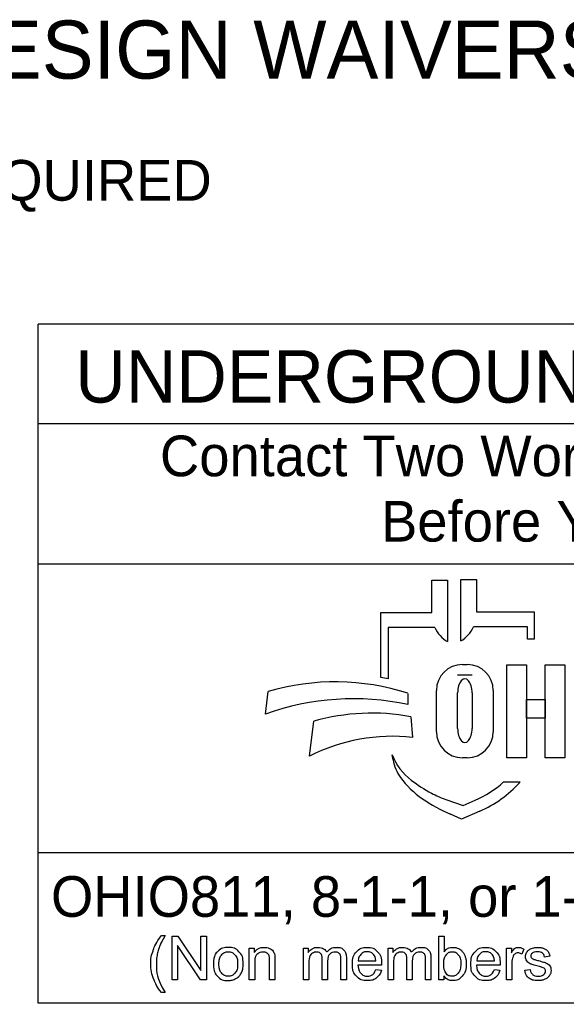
# Model space of a CAD drawing. Extents: x 0 to 34, y 0 to 22.
# Drawn here: x 2.914 to 4.796, y 2.143 to 5.529 of the extents above; entities that cross this region are included whole.
import ezdxf

# ---------------------------------------------------------------- set-up
doc = ezdxf.new("R2010")
doc.units = 0
doc.layers.add('SH_Data', color=7, linetype='Continuous')
doc.layers.add('SH_Text', color=7, linetype='Continuous')

msp = doc.modelspace()

# ---------------------------------------------------------------- linework, layer by layer
at = {"layer": 'SH_Data'}
for p, q in [((2.9775, 2.1428), (2.9775, 4.4803)), ((7.2275, 4.4803), (2.9775, 4.4803)), ((2.9775, 4.1387), (7.2275, 4.1387)), ((2.9775, 3.6553), (7.2275, 3.6553)), ((7.2275, 2.6607), (2.9775, 2.6607)), ((7.2275, 2.1428), (2.9775, 2.1428))]:
    msp.add_line(p, q, dxfattribs=at)
at = {"layer": 'SH_Text'}
for p, q in [((4.3335, 3.4883), (4.3335, 3.5998)), ((4.3335, 3.5998), (4.3872, 3.5998)), ((4.3872, 3.5998), (4.3872, 3.3877)), ((4.4329, 3.39), (4.4329, 3.6021)), ((4.4329, 3.6021), (4.4865, 3.6021)), ((4.4865, 3.6021), (4.4865, 3.4906)), ((4.1576, 3.2644), (4.1576, 3.4883)), ((4.1576, 3.4883), (4.3335, 3.4883)), ((4.4865, 3.4906), (4.6857, 3.4906)), ((4.6857, 3.4906), (4.6857, 3.3968)), ((4.1828, 3.4369), (4.1828, 3.26)), ((4.3439, 3.4369), (4.1828, 3.4369)), ((4.6625, 3.4392), (4.4761, 3.4392)), ((4.6625, 3.3968), (4.6625, 3.4392)), ((4.6857, 3.3968), (4.6625, 3.3968)), ((4.4385, 3.3091), (4.4551, 3.3091)), ((4.4718, 3.2721), (4.422, 3.2721)), ((4.3491, 3.0776), (4.3491, 3.2196)), ((4.5445, 3.2196), (4.5445, 3.0776)), ((3.7602, 3.1381), (3.7696, 3.2162)), ((4.2509, 3.2097), (4.2509, 3.1709)), ((4.422, 3.089), (4.422, 3.2114)), ((4.4718, 3.2114), (4.4718, 3.089)), ((4.2608, 3.1291), (4.2671, 3.0582)), ((3.912, 2.9936), (3.9267, 3.1137)), ((4.1997, 2.9807), (4.1967, 2.9986)), ((4.4551, 2.9882), (4.4385, 2.9882)), ((4.58, 2.9048), (4.6375, 2.9048)), ((4.3816, 2.8444), (4.441, 2.8239)), ((4.441, 2.8239), (4.4821, 2.8417)), ((4.435, 2.7769), (4.3976, 2.7934)), ((4.4983, 2.8044), (4.435, 2.7769))]:
    msp.add_line(p, q, dxfattribs=at)
for points in [[(4.591, 3.3081), (4.6589, 3.3081), (4.6589, 2.9881), (4.591, 2.9881)], [(4.7231, 3.3081), (4.7911, 3.3081), (4.7911, 2.9881), (4.7231, 2.9881)], [(4.6589, 3.1882), (4.7231, 3.1882), (4.7231, 3.1242), (4.6589, 3.1242)]]:
    msp.add_lwpolyline(points, close=True, dxfattribs=at)
for points in [[(3.4021, 2.3766), (3.4153, 2.3766)], [(3.4389, 2.2239), (3.4389, 2.3741), (3.4592, 2.3741), (3.5382, 2.2561), (3.5382, 2.3741), (3.5572, 2.3741), (3.5572, 2.2239), (3.5369, 2.2239), (3.4579, 2.3419), (3.4579, 2.2239), (3.4389, 2.2239)], [(4.3743, 2.2239), (4.3573, 2.2239), (4.3573, 2.3741), (4.3757, 2.3741), (4.3757, 2.3206)], [(3.7048, 2.2239), (3.7048, 2.3328), (3.7214, 2.3328), (3.7214, 2.3173)], [(3.8912, 2.2239), (3.8912, 2.3328), (3.9077, 2.3328), (3.9077, 2.3174)], [(4.1826, 2.2239), (4.1826, 2.3328), (4.1991, 2.3328), (4.1991, 2.3174)], [(4.5904, 2.2239), (4.5904, 2.3328), (4.607, 2.3328), (4.607, 2.3163)], [(4.6495, 2.3293), (4.643, 2.3122)], [(4.7394, 2.3046), (4.7213, 2.3022)], [(3.7233, 2.2833), (3.7233, 2.2239), (3.7048, 2.2239)], [(3.7932, 2.2908), (3.7932, 2.2239), (3.7748, 2.2239), (3.7748, 2.2901)], [(3.9097, 2.2803), (3.9097, 2.2239), (3.8912, 2.2239)], [(3.9743, 2.2871), (3.9743, 2.2239), (3.9559, 2.2239), (3.9559, 2.2946)], [(4.0388, 2.2986), (4.0388, 2.2239), (4.0203, 2.2239), (4.0203, 2.2924)], [(4.16, 2.2736), (4.0788, 2.2736)], [(4.0799, 2.2887), (4.1406, 2.2887)], [(4.201, 2.2803), (4.201, 2.2239), (4.1826, 2.2239)], [(4.2657, 2.2871), (4.2657, 2.2239), (4.2473, 2.2239), (4.2473, 2.2946)], [(4.3301, 2.2986), (4.3301, 2.2239), (4.3117, 2.2239), (4.3117, 2.2924)], [(4.568, 2.2736), (4.4868, 2.2736)], [(4.4879, 2.2887), (4.5486, 2.2887)], [(4.6088, 2.2809), (4.6088, 2.2239), (4.5904, 2.2239)], [(4.1404, 2.2591), (4.1595, 2.2567)], [(4.3743, 2.2375), (4.3743, 2.2239)], [(4.5484, 2.2591), (4.5675, 2.2567)], [(4.653, 2.2564), (4.6712, 2.2593)], [(3.4153, 2.1798), (3.4021, 2.1798)]]:
    msp.add_lwpolyline(points, dxfattribs=at)
for centre, radius, start, end in [((4.4353, 3.4736), 0.0985, 201.9296, 240.7469), ((4.3847, 3.476), 0.0985, 299.2531, 338.0704), ((4.4385, 3.2196), 0.0895, 90, 180), ((4.4551, 3.2196), 0.0895, 0, 90), ((4.0295, 2.4554), 0.8191, 79.2074, 81.0007), ((3.9997, 2.4302), 0.8191, 72.1402, 106.3144), ((4.0628, 2.2991), 0.8919, 77.8238, 109.8274), ((4.1267, 2.4094), 0.7322, 79.44, 105.8467), ((4.1987, 2.4262), 0.6357, 83.8248, 116.8021), ((4.4385, 3.0776), 0.0895, 180, 270), ((4.4551, 3.0776), 0.0895, 270, 0), ((4.3841, 3.0707), 0.2008, 201.0457, 232.5314), ((4.341, 3.0048), 0.1433, 189.6817, 216.0884), ((4.4747, 3.1022), 0.3088, 216.0884, 235.7167), ((4.5766, 3.3219), 0.5173, 232.5314, 241.794), ((4.3387, 3.1722), 0.3602, 293.4582, 312.0712), ((4.3387, 3.1722), 0.401, 293.4582, 317.8286), ((4.6412, 3.3465), 0.6044, 235.7167, 246.2325), ((4.4914, 3.1631), 0.3371, 241.794, 250.9821)]:
    msp.add_arc(centre, radius, start, end, dxfattribs=at)
for centre, start_param, end_param in [((4.4469, 3.2114), 4.712389, 7.853982), ((4.4469, 3.089), 1.570796, 4.712389)]:
    msp.add_ellipse(centre, major_axis=(0, 0.0484), ratio=0.514403, start_param=start_param, end_param=end_param, dxfattribs=at)
for points in [[(3.4021, 2.1798), (3.3869, 2.199), (3.3763, 2.2248), (3.3657, 2.2506), (3.3657, 2.2783), (3.3657, 2.3026), (3.3736, 2.325), (3.3829, 2.3509), (3.4021, 2.3766)], [(3.4153, 2.3766), (3.4029, 2.3553), (3.3989, 2.3462), (3.3927, 2.332), (3.3891, 2.3167), (3.3847, 2.2975), (3.3847, 2.2782), (3.3847, 2.2289), (3.4153, 2.1798)], [(3.5814, 2.2783), (3.5814, 2.3085), (3.5981, 2.3231), (3.6122, 2.3352), (3.6323, 2.3352), (3.6547, 2.3352), (3.669, 2.3205), (3.6832, 2.3058), (3.6832, 2.2799), (3.6832, 2.2589), (3.6769, 2.2469), (3.6706, 2.2348), (3.6586, 2.2282), (3.6466, 2.2215), (3.6323, 2.2215), (3.6095, 2.2215), (3.5954, 2.2362), (3.5814, 2.2508), (3.5814, 2.2783)], [(3.6003, 2.2783), (3.6003, 2.2574), (3.6094, 2.247), (3.6185, 2.2366), (3.6323, 2.2366), (3.646, 2.2366), (3.6551, 2.2471), (3.6642, 2.2575), (3.6642, 2.279), (3.6642, 2.2991), (3.6551, 2.3095), (3.6459, 2.3199), (3.6323, 2.3199), (3.6185, 2.3199), (3.6094, 2.3096), (3.6003, 2.2992), (3.6003, 2.2783)], [(3.7214, 2.3173), (3.7334, 2.3352), (3.756, 2.3352), (3.7659, 2.3352), (3.7741, 2.3316), (3.7823, 2.3281), (3.7864, 2.3224), (3.7905, 2.3166), (3.7922, 2.3087), (3.7932, 2.3036), (3.7932, 2.2908)], [(3.7748, 2.2901), (3.7748, 2.3013), (3.7726, 2.3069), (3.7705, 2.3125), (3.765, 2.3158), (3.7595, 2.3191), (3.7521, 2.3191), (3.7404, 2.3191), (3.7318, 2.3117), (3.7233, 2.3042), (3.7233, 2.2833)], [(3.9077, 2.3174), (3.9128, 2.3254), (3.9214, 2.3303), (3.9299, 2.3352), (3.9407, 2.3352), (3.9528, 2.3352), (3.9606, 2.3301), (3.9683, 2.3251), (3.9715, 2.3161), (3.9844, 2.3352), (4.0051, 2.3352), (4.0213, 2.3352), (4.03, 2.3262), (4.0388, 2.3172), (4.0388, 2.2986)], [(3.9559, 2.2946), (3.9559, 2.3069), (3.9514, 2.313), (3.9469, 2.3191), (3.9366, 2.3191), (3.9288, 2.3191), (3.9222, 2.315), (3.9156, 2.311), (3.9126, 2.3031), (3.9097, 2.2952), (3.9097, 2.2803)], [(4.0203, 2.2924), (4.0203, 2.3035), (4.0185, 2.3083), (4.0168, 2.3132), (4.012, 2.3162), (4.0073, 2.3191), (4.001, 2.3191), (3.9895, 2.3191), (3.9819, 2.3115), (3.9743, 2.3039), (3.9743, 2.2871)], [(4.1595, 2.2567), (4.155, 2.24), (4.1428, 2.2307), (4.1306, 2.2215), (4.1117, 2.2215), (4.0878, 2.2215), (4.0738, 2.2362), (4.0598, 2.2509), (4.0598, 2.2774), (4.0598, 2.3049), (4.074, 2.32), (4.0881, 2.3352), (4.1106, 2.3352), (4.1324, 2.3352), (4.1463, 2.3203), (4.1601, 2.3055), (4.1601, 2.2785), (4.1601, 2.2769), (4.16, 2.2736)], [(4.1406, 2.2887), (4.1394, 2.3025), (4.1337, 2.3094), (4.1249, 2.3201), (4.1108, 2.3201), (4.0981, 2.3201), (4.0894, 2.3115), (4.0808, 2.303), (4.0799, 2.2887)], [(4.1991, 2.3174), (4.2042, 2.3254), (4.2127, 2.3303), (4.2212, 2.3352), (4.2321, 2.3352), (4.2442, 2.3352), (4.2519, 2.3301), (4.2597, 2.3251), (4.2628, 2.3161), (4.2758, 2.3352), (4.2965, 2.3352), (4.3127, 2.3352), (4.3214, 2.3262), (4.3301, 2.3172), (4.3301, 2.2986)], [(4.2473, 2.2946), (4.2473, 2.3069), (4.2428, 2.313), (4.2383, 2.3191), (4.228, 2.3191), (4.2202, 2.3191), (4.2136, 2.315), (4.207, 2.311), (4.204, 2.3031), (4.201, 2.2952), (4.201, 2.2803)], [(4.3117, 2.2924), (4.3117, 2.3035), (4.3099, 2.3083), (4.3081, 2.3132), (4.3034, 2.3162), (4.2987, 2.3191), (4.2923, 2.3191), (4.2809, 2.3191), (4.2733, 2.3115), (4.2657, 2.3039), (4.2657, 2.2871)], [(4.3741, 2.2792), (4.3741, 2.2596), (4.3794, 2.2509), (4.3881, 2.2366), (4.4029, 2.2366), (4.415, 2.2366), (4.4238, 2.2471), (4.4326, 2.2576), (4.4326, 2.2784), (4.4326, 2.2998), (4.4241, 2.3099), (4.4157, 2.3201), (4.4038, 2.3201), (4.3917, 2.3201), (4.3829, 2.3096), (4.3741, 2.299), (4.3741, 2.2792)], [(4.3757, 2.3206), (4.3874, 2.3352), (4.4055, 2.3352), (4.4155, 2.3352), (4.4245, 2.3311), (4.4335, 2.3271), (4.4392, 2.3198), (4.445, 2.3124), (4.4483, 2.3021), (4.4516, 2.2918), (4.4516, 2.28), (4.4516, 2.252), (4.4378, 2.2368), (4.4239, 2.2215), (4.4046, 2.2215), (4.3853, 2.2215), (4.3743, 2.2375)], [(4.5675, 2.2567), (4.563, 2.24), (4.5508, 2.2307), (4.5386, 2.2215), (4.5196, 2.2215), (4.4958, 2.2215), (4.4818, 2.2362), (4.4678, 2.2509), (4.4678, 2.2774), (4.4678, 2.3049), (4.482, 2.32), (4.4961, 2.3352), (4.5186, 2.3352), (4.5404, 2.3352), (4.5543, 2.3203), (4.5681, 2.3055), (4.5681, 2.2785), (4.5681, 2.2769), (4.568, 2.2736)], [(4.5486, 2.2887), (4.5474, 2.3025), (4.5417, 2.3094), (4.5328, 2.3201), (4.5188, 2.3201), (4.5061, 2.3201), (4.4974, 2.3115), (4.4888, 2.303), (4.4879, 2.2887)], [(4.607, 2.3163), (4.6133, 2.3278), (4.6187, 2.3315), (4.6241, 2.3352), (4.6305, 2.3352), (4.6398, 2.3352), (4.6495, 2.3293)], [(4.643, 2.3122), (4.6363, 2.3162), (4.6295, 2.3162), (4.6235, 2.3162), (4.6187, 2.3125), (4.6139, 2.3089), (4.6119, 2.3024), (4.6088, 2.2926), (4.6088, 2.2809)], [(4.7213, 2.3022), (4.7201, 2.3106), (4.7142, 2.3153), (4.7083, 2.3201), (4.6975, 2.3201), (4.6848, 2.3201), (4.6794, 2.3159), (4.6739, 2.3116), (4.6739, 2.306), (4.6739, 2.3024), (4.6762, 2.2995), (4.6785, 2.2966), (4.6833, 2.2946), (4.686, 2.2936), (4.6996, 2.2899), (4.7192, 2.2847), (4.7269, 2.2813), (4.7347, 2.278), (4.7391, 2.2717), (4.7435, 2.2653), (4.7435, 2.2559), (4.7435, 2.2467), (4.7381, 2.2386), (4.7327, 2.2304), (4.7226, 2.226), (4.7124, 2.2215), (4.6996, 2.2215), (4.6784, 2.2215), (4.6672, 2.2303), (4.6561, 2.2391), (4.653, 2.2564)], [(4.6712, 2.2593), (4.6727, 2.2483), (4.6798, 2.2425), (4.6868, 2.2366), (4.6995, 2.2366), (4.7122, 2.2366), (4.7184, 2.2418), (4.7245, 2.247), (4.7245, 2.254), (4.7245, 2.2602), (4.7191, 2.2638), (4.7153, 2.2663), (4.7002, 2.2701), (4.6799, 2.2752), (4.672, 2.2789), (4.6642, 2.2827), (4.6601, 2.2893), (4.6561, 2.2959), (4.6561, 2.3038), (4.6561, 2.3111), (4.6594, 2.3173), (4.6628, 2.3235), (4.6685, 2.3276), (4.6728, 2.3308), (4.6803, 2.333), (4.6877, 2.3352), (4.6962, 2.3352), (4.709, 2.3352), (4.7187, 2.3315), (4.7284, 2.3278), (4.733, 2.3215), (4.7377, 2.3152), (4.7394, 2.3046)], [(4.0788, 2.2736), (4.0799, 2.2557), (4.089, 2.2462), (4.0981, 2.2366), (4.1117, 2.2366), (4.1219, 2.2366), (4.1291, 2.242), (4.1362, 2.2473), (4.1404, 2.2591)], [(4.4868, 2.2736), (4.4879, 2.2557), (4.497, 2.2462), (4.5061, 2.2366), (4.5197, 2.2366), (4.5299, 2.2366), (4.537, 2.242), (4.5442, 2.2473), (4.5484, 2.2591)]]:
    msp.add_open_spline(points, degree=3, dxfattribs=at)

# ---------------------------------------------------------------- texts
for s, height, p in [('ADA DESIGN WAIVERS', 0.2, (1.9944, 5.3256)), ('NONE REQUIRED', 0.14, (1.9944, 4.9056)), ('UNDERGROUND UTILITIES', 0.18, (3.1057, 4.2106)), ('Contact Two Working Days', 0.14, (3.3972, 3.9571)), ('Before You Dig', 0.14, (4.1583, 3.7321)), ('OHIO811, 8-1-1, or 1-800-362-2764', 0.14, (3.022, 2.4406))]:
    msp.add_text(s, height=height, dxfattribs=at).set_placement(p)

doc.saveas('drawing.dxf')
